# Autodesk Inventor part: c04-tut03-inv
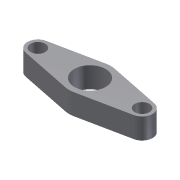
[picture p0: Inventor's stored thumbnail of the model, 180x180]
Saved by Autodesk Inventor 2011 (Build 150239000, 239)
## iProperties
Created: 2008-01
Part Number: c04-tut03-inv
Document SubType Name: Modeling
Designer: CADSoft
Density: 1 g/cm^3
Author: CADSoft
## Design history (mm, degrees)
sketch "Sketch1"
  geometry: L1 (-26, 4.899)-(-2, 9.798); L2 (2, 9.798)-(26, 4.899); L3 (26, -4.899)-(2, -9.798); L4 (-26, -4.899)-(-2, -9.798); C1 r 3.5 at (-25, 0); C2 r 3.5 at (25, 0); C3 r 7.5 at (0, 0); A1 r 5 centre (-25, 0) between (-26, 4.899) and (-26, -4.899); A2 r 5 centre (25, 0) between (26, -4.899) and (26, 4.899); A3 r 10 centre (0, 0) between (-2, -9.798) and (2, -9.798); A4 r 10 centre (0, 0) between (2, 9.798) and (-2, 9.798); 1 further point
  constraints: 8 end point, 8 point on circle, 8 tangent, 7 centre point, 4 coincident, 2 equal radius, 2 horizontal alignment, 1 equal length
  dimensions: "d0" = 50 distance of C2.centre C1.centre; "d1" = 7 diameter of C1; "d2" = 5 radius of A1; "d3" = 10 radius of A4; "d4" = 10 radius of A3; "d5" = 15 diameter of C3; "d6" = 25 distance of A1.centre point (0, 0) (derived)
extrude "Extrusion1" new body sketch "Sketch1" distance "d7" = 10; taper "d8" = 0 deg
body "Solid1"
